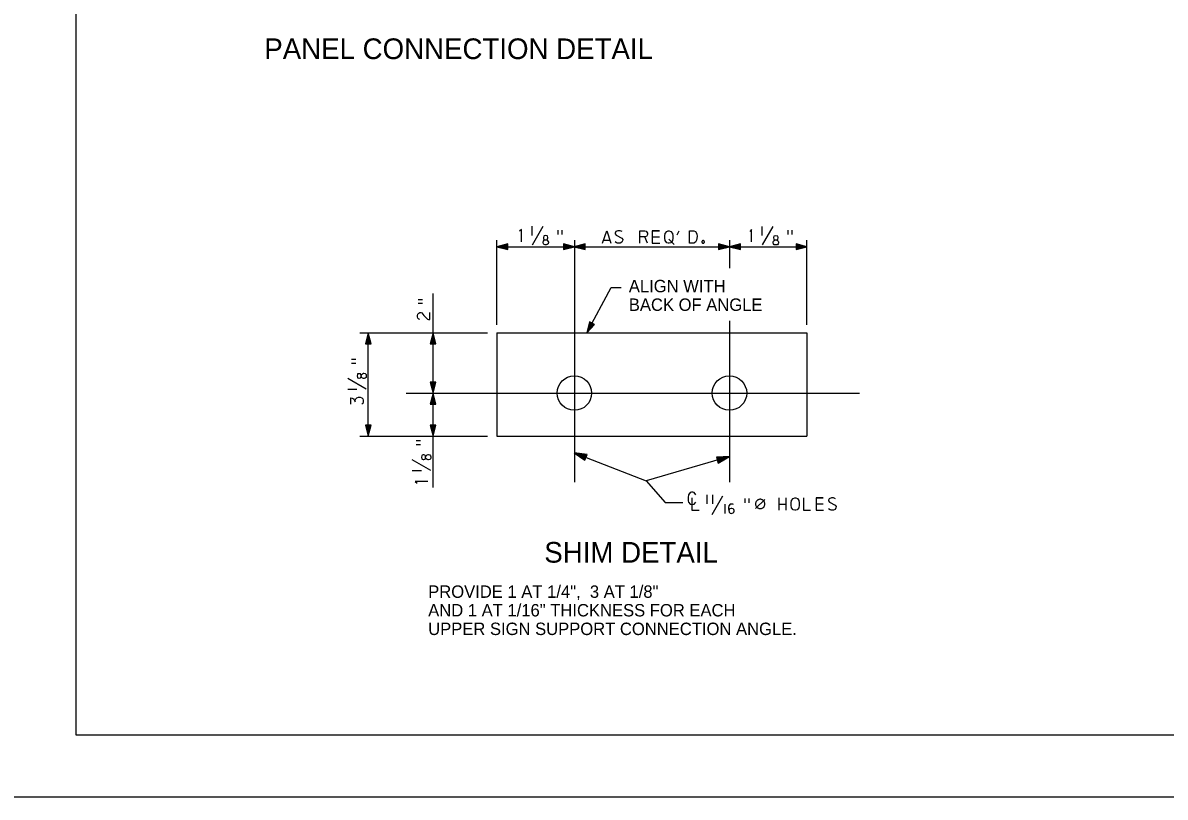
# Model space of a CAD drawing. Extents: x 3831399 to 3833095, y 499014 to 500202.
# Drawn here: x 3832267.3 to 3832543.5, y 499014 to 499201.4 of the extents above; entities that cross this region are included whole.
import ezdxf

# ---------------------------------------------------------------- set-up
doc = ezdxf.new("R2010")
doc.units = 0
for name, color, linetype in [('10', 7, 'Continuous'), ('11', 7, 'Continuous'), ('2', 7, 'Continuous'), ('21', 7, 'Continuous'), ('Default', 7, 'Continuous'), ('PLT-BNDY', 7, 'Continuous')]:
    doc.layers.add(name, color=color, linetype=linetype)

msp = doc.modelspace()

# ---------------------------------------------------------------- linework, layer by layer
at = {"layer": '10'}
for p, q in [((3832390.41, 499149.9), (3832390.41, 499152.15)), ((3832390.53, 499147.63), (3832393.08, 499152.15)), ((3832446.05, 499149.88), (3832446.05, 499152.12)), ((3832446.17, 499147.61), (3832448.72, 499152.12)), ((3832387.89, 499151.39), (3832387.41, 499150.92)), ((3832387.89, 499148.39), (3832387.89, 499151.39)), ((3832396.74, 499150.14), (3832396.74, 499151.2)), ((3832397.69, 499150.14), (3832397.69, 499151.2)), ((3832418.35, 499148.05), (3832417.67, 499149.58)), ((3832419.49, 499151.05), (3832421.21, 499151.05)), ((3832419.49, 499149.56), (3832421.21, 499149.56)), ((3832419.49, 499149.56), (3832421.21, 499149.56)), ((3832425.49, 499150.06), (3832425.96, 499151.05)), ((3832443.52, 499151.36), (3832443.05, 499150.89)), ((3832443.52, 499148.36), (3832443.52, 499151.36)), ((3832452.38, 499150.11), (3832452.38, 499151.17)), ((3832453.33, 499150.11), (3832453.33, 499151.17)), ((3832384.54, 499147.87), (3832381.89, 499147.2)), ((3832381.89, 499147.2), (3832384.54, 499146.54)), ((3832381.9, 499128.27), (3832381.9, 499148.77)), ((3832381.9, 499147.2), (3832400.65, 499147.2)), ((3832384.38, 499147.66), (3832382.54, 499147.2)), ((3832382.54, 499147.2), (3832384.38, 499146.74)), ((3832384.23, 499147.46), (3832383.19, 499147.2)), ((3832383.19, 499147.2), (3832384.23, 499146.94)), ((3832384.16, 499147.29), (3832383.83, 499147.2)), ((3832383.83, 499147.2), (3832384.15, 499147.12)), ((3832384.23, 499146.94), (3832384.23, 499147.46)), ((3832384.38, 499146.74), (3832384.38, 499147.66)), ((3832384.54, 499146.54), (3832384.54, 499147.87)), ((3832400.65, 499147.2), (3832398, 499147.86)), ((3832398, 499147.86), (3832398, 499146.54)), ((3832398, 499146.54), (3832400.65, 499147.2)), ((3832400, 499147.2), (3832398.16, 499147.66)), ((3832398.16, 499147.66), (3832398.16, 499146.74)), ((3832398.16, 499146.74), (3832400, 499147.2)), ((3832399.36, 499147.2), (3832398.32, 499147.46)), ((3832398.32, 499147.46), (3832398.32, 499146.94)), ((3832398.32, 499146.94), (3832399.36, 499147.2)), ((3832398.38, 499147.12), (3832398.71, 499147.2)), ((3832398.71, 499147.2), (3832398.4, 499147.28)), ((3832403.29, 499147.87), (3832400.64, 499147.2)), ((3832400.64, 499147.2), (3832403.29, 499146.54)), ((3832400.65, 499147.2), (3832438.14, 499147.2)), ((3832403.13, 499147.66), (3832401.29, 499147.2)), ((3832401.29, 499147.2), (3832403.13, 499146.74)), ((3832402.97, 499147.46), (3832401.94, 499147.2)), ((3832401.94, 499147.2), (3832402.97, 499146.94)), ((3832402.91, 499147.29), (3832402.58, 499147.2)), ((3832402.58, 499147.2), (3832402.9, 499147.12)), ((3832402.97, 499146.94), (3832402.97, 499147.46)), ((3832403.13, 499146.74), (3832403.13, 499147.66)), ((3832403.29, 499146.54), (3832403.29, 499147.87)), ((3832407.72, 499148.76), (3832409.21, 499148.76)), ((3832424.8, 499147.74), (3832423.48, 499148.99)), ((3832438.15, 499147.2), (3832435.5, 499147.86)), ((3832435.5, 499147.86), (3832435.5, 499146.54)), ((3832435.5, 499146.54), (3832438.15, 499147.2)), ((3832437.5, 499147.2), (3832435.66, 499147.66)), ((3832435.66, 499147.66), (3832435.66, 499146.74)), ((3832435.66, 499146.74), (3832437.5, 499147.2)), ((3832436.85, 499147.2), (3832435.82, 499147.46)), ((3832435.82, 499147.46), (3832435.82, 499146.94)), ((3832435.82, 499146.94), (3832436.85, 499147.2)), ((3832435.88, 499147.12), (3832436.21, 499147.2)), ((3832436.21, 499147.2), (3832435.89, 499147.28)), ((3832440.79, 499147.87), (3832438.14, 499147.2)), ((3832438.14, 499147.2), (3832456.89, 499147.2)), ((3832438.14, 499147.2), (3832440.79, 499146.54)), ((3832440.63, 499147.66), (3832438.79, 499147.2)), ((3832438.79, 499147.2), (3832440.63, 499146.74)), ((3832440.47, 499147.46), (3832439.43, 499147.2)), ((3832439.43, 499147.2), (3832440.47, 499146.94)), ((3832440.41, 499147.29), (3832440.08, 499147.2)), ((3832440.08, 499147.2), (3832440.39, 499147.12)), ((3832440.47, 499146.94), (3832440.47, 499147.46)), ((3832440.63, 499146.74), (3832440.63, 499147.66)), ((3832440.79, 499146.54), (3832440.79, 499147.87)), ((3832456.9, 499147.2), (3832454.25, 499147.86)), ((3832454.25, 499147.86), (3832454.25, 499146.54)), ((3832454.25, 499146.54), (3832456.9, 499147.2)), ((3832456.25, 499147.2), (3832454.41, 499147.66)), ((3832454.41, 499147.66), (3832454.41, 499146.74)), ((3832454.41, 499146.74), (3832456.25, 499147.2)), ((3832455.6, 499147.2), (3832454.57, 499147.46)), ((3832454.57, 499147.46), (3832454.57, 499146.94)), ((3832454.57, 499146.94), (3832455.6, 499147.2)), ((3832454.63, 499147.12), (3832454.96, 499147.2)), ((3832454.96, 499147.2), (3832454.64, 499147.28)), ((3832456.89, 499128.27), (3832456.89, 499148.77)), ((3832366.47, 499126.36), (3832366.47, 499135.86)), ((3832403.67, 499126.36), (3832409.53, 499137.36)), ((3832409.53, 499137.36), (3832411.96, 499137.36)), ((3832363.93, 499134.37), (3832362.87, 499134.37)), ((3832363.93, 499133.42), (3832362.87, 499133.42)), ((3832404.33, 499129), (3832403.67, 499126.36)), ((3832403.67, 499126.36), (3832405.49, 499128.38)), ((3832404.43, 499128.77), (3832403.97, 499126.93)), ((3832403.97, 499126.93), (3832405.24, 499128.33)), ((3832404.53, 499128.53), (3832404.27, 499127.5)), ((3832404.27, 499127.5), (3832404.99, 499128.29)), ((3832405.49, 499128.38), (3832404.33, 499129)), ((3832405.24, 499128.33), (3832404.43, 499128.77)), ((3832404.99, 499128.29), (3832404.53, 499128.53)), ((3832404.66, 499128.4), (3832404.58, 499128.07)), ((3832404.58, 499128.07), (3832404.8, 499128.31)), ((3832348.8, 499126.36), (3832379.65, 499126.36)), ((3832350.82, 499126.36), (3832350.16, 499123.71)), ((3832350.82, 499125.71), (3832350.36, 499123.87)), ((3832350.82, 499125.07), (3832350.56, 499124.03)), ((3832350.82, 499124.42), (3832350.74, 499124.11)), ((3832350.82, 499101.36), (3832350.82, 499126.36)), ((3832351.48, 499123.71), (3832350.82, 499126.36)), ((3832351.28, 499123.87), (3832350.82, 499125.71)), ((3832351.08, 499124.03), (3832350.82, 499125.07)), ((3832350.9, 499124.09), (3832350.82, 499124.42)), ((3832366.47, 499126.36), (3832365.81, 499123.71)), ((3832366.47, 499125.71), (3832366.01, 499123.87)), ((3832366.47, 499125.07), (3832366.21, 499124.03)), ((3832366.47, 499124.42), (3832366.39, 499124.11)), ((3832366.47, 499111.77), (3832366.47, 499126.36)), ((3832367.13, 499123.71), (3832366.47, 499126.36)), ((3832366.93, 499123.87), (3832366.47, 499125.71)), ((3832366.73, 499124.03), (3832366.47, 499125.07)), ((3832366.55, 499124.09), (3832366.47, 499124.42)), ((3832350.16, 499123.71), (3832351.48, 499123.71)), ((3832350.36, 499123.87), (3832351.28, 499123.87)), ((3832350.56, 499124.03), (3832351.08, 499124.03)), ((3832365.81, 499123.71), (3832367.13, 499123.71)), ((3832366.01, 499123.87), (3832366.93, 499123.87)), ((3832366.21, 499124.03), (3832366.73, 499124.03)), ((3832347.83, 499119.91), (3832346.77, 499119.91)), ((3832347.83, 499118.96), (3832346.77, 499118.96)), ((3832350.34, 499112.75), (3832345.83, 499115.3)), ((3832365.8, 499114.42), (3832366.47, 499111.77)), ((3832367.13, 499114.42), (3832365.8, 499114.42)), ((3832366, 499114.26), (3832366.47, 499112.42)), ((3832366.93, 499114.26), (3832366, 499114.26)), ((3832366.21, 499114.1), (3832366.47, 499113.06)), ((3832366.73, 499114.1), (3832366.21, 499114.1)), ((3832366.38, 499114.04), (3832366.47, 499113.71)), ((3832366.47, 499111.77), (3832367.13, 499114.42)), ((3832366.47, 499112.42), (3832366.93, 499114.26)), ((3832366.47, 499113.06), (3832366.73, 499114.1)), ((3832366.47, 499113.71), (3832366.54, 499114.03)), ((3832348.07, 499112.63), (3832345.83, 499112.63)), ((3832366.47, 499111.78), (3832365.81, 499109.13)), ((3832366.47, 499111.13), (3832366.01, 499109.29)), ((3832366.47, 499110.49), (3832366.21, 499109.45)), ((3832367.13, 499109.13), (3832366.47, 499111.78)), ((3832366.47, 499101.36), (3832366.47, 499111.77)), ((3832366.93, 499109.29), (3832366.47, 499111.13)), ((3832366.73, 499109.45), (3832366.47, 499110.49)), ((3832365.81, 499109.13), (3832367.13, 499109.13)), ((3832366.01, 499109.29), (3832366.93, 499109.29)), ((3832366.21, 499109.45), (3832366.73, 499109.45)), ((3832366.47, 499109.84), (3832366.39, 499109.52)), ((3832366.55, 499109.51), (3832366.47, 499109.84)), ((3832350.16, 499104), (3832350.82, 499101.35)), ((3832351.48, 499104), (3832350.16, 499104)), ((3832350.36, 499103.84), (3832350.82, 499102)), ((3832351.28, 499103.84), (3832350.36, 499103.84)), ((3832350.56, 499103.69), (3832350.82, 499102.65)), ((3832351.08, 499103.69), (3832350.56, 499103.69)), ((3832350.73, 499103.62), (3832350.82, 499103.29)), ((3832350.82, 499101.35), (3832351.48, 499104)), ((3832350.82, 499102), (3832351.28, 499103.84)), ((3832350.82, 499102.65), (3832351.08, 499103.69)), ((3832350.82, 499103.29), (3832350.89, 499103.61)), ((3832365.8, 499104), (3832366.47, 499101.35)), ((3832367.13, 499104), (3832365.8, 499104)), ((3832366, 499103.84), (3832366.47, 499102)), ((3832366.93, 499103.84), (3832366, 499103.84)), ((3832366.21, 499103.69), (3832366.47, 499102.65)), ((3832366.73, 499103.69), (3832366.21, 499103.69)), ((3832366.38, 499103.62), (3832366.47, 499103.29)), ((3832366.47, 499101.35), (3832367.13, 499104)), ((3832366.47, 499102), (3832366.93, 499103.84)), ((3832366.47, 499102.65), (3832366.73, 499103.69)), ((3832366.47, 499103.29), (3832366.54, 499103.61)), ((3832348.8, 499101.36), (3832379.65, 499101.36)), ((3832363.43, 499100.23), (3832362.37, 499100.23)), ((3832366.47, 499088.92), (3832366.47, 499101.36)), ((3832363.43, 499099.29), (3832362.37, 499099.29)), ((3832400.64, 499097.3), (3832418, 499090.58)), ((3832400.64, 499097.3), (3832403.17, 499095.52)), ((3832403.71, 499096.92), (3832400.64, 499097.3)), ((3832401.33, 499097.04), (3832403.09, 499095.8)), ((3832403.46, 499096.77), (3832401.33, 499097.04)), ((3832403.22, 499096.63), (3832402.01, 499096.78)), ((3832402.01, 499096.78), (3832403, 499096.07)), ((3832403.09, 499095.8), (3832403.46, 499096.77)), ((3832403.17, 499095.52), (3832403.71, 499096.92)), ((3832365.94, 499093.07), (3832361.42, 499095.63)), ((3832402.69, 499096.51), (3832402.99, 499096.3)), ((3832403.08, 499096.46), (3832402.69, 499096.51)), ((3832403, 499096.07), (3832403.22, 499096.63)), ((3832438.15, 499096.44), (3832418, 499090.58)), ((3832438.15, 499096.44), (3832435.02, 499096.32)), ((3832435.02, 499096.32), (3832435.44, 499094.86)), ((3832437.43, 499096.23), (3832435.25, 499096.15)), ((3832435.25, 499096.15), (3832435.55, 499095.14)), ((3832435.44, 499094.86), (3832438.15, 499096.44)), ((3832436.72, 499096.03), (3832435.49, 499095.98)), ((3832435.49, 499095.98), (3832435.66, 499095.41)), ((3832435.55, 499095.14), (3832437.43, 499096.23)), ((3832436.01, 499095.82), (3832435.64, 499095.81)), ((3832435.66, 499095.41), (3832436.72, 499096.03)), ((3832435.67, 499095.62), (3832436.01, 499095.82)), ((3832363.67, 499092.96), (3832361.42, 499092.96)), ((3832365.18, 499090.43), (3832362.18, 499090.43)), ((3832362.18, 499090.43), (3832362.65, 499089.96)), ((3832418, 499090.58), (3832422.62, 499085.33)), ((3832432.8, 499084.96), (3832432.8, 499087.2)), ((3832434.01, 499082.41), (3832436.56, 499086.92)), ((3832434.1, 499084.96), (3832434.1, 499087.2)), ((3832441.97, 499085.2), (3832441.97, 499086.26)), ((3832442.91, 499085.2), (3832442.91, 499086.26)), ((3832444.47, 499083.83), (3832446.71, 499086.07)), ((3832450.09, 499086.45), (3832450.09, 499083.45)), ((3832451.79, 499086.45), (3832451.79, 499083.45)), ((3832459.09, 499086.45), (3832460.82, 499086.45)), ((3832422.62, 499085.33), (3832426.86, 499085.33)), ((3832437.08, 499082.69), (3832437.08, 499084.94)), ((3832450.09, 499084.94), (3832451.79, 499084.94)), ((3832459.09, 499084.96), (3832460.82, 499084.96)), ((3832459.09, 499084.96), (3832460.82, 499084.96))]:
    msp.add_line(p, q, dxfattribs=at)
for points in [[(3832393.84, 499148.89), (3832394.1, 499148.96), (3832394.19, 499149.07), (3832394.26, 499149.33), (3832394.26, 499149.45), (3832394.19, 499149.74), (3832394.08, 499149.81), (3832393.72, 499149.88), (3832393.34, 499149.81), (3832393.25, 499149.74), (3832393.15, 499149.45), (3832393.15, 499149.33), (3832393.22, 499149.07), (3832393.34, 499148.96), (3832393.6, 499148.89), (3832393.84, 499148.89), (3832394.1, 499148.74), (3832394.26, 499148.53), (3832394.36, 499148.29), (3832394.36, 499148.2), (3832394.29, 499147.89), (3832394.1, 499147.7), (3832393.84, 499147.63), (3832393.6, 499147.63), (3832393.34, 499147.7), (3832393.15, 499147.89), (3832393.08, 499148.18), (3832393.08, 499148.29), (3832393.18, 499148.53), (3832393.34, 499148.74), (3832393.6, 499148.89)], [(3832407.49, 499148.05), (3832408.48, 499151.05), (3832409.45, 499148.05)], [(3832412.21, 499150.84), (3832411.74, 499151.05), (3832411.19, 499151.05), (3832410.7, 499150.84), (3832410.49, 499150.46), (3832410.49, 499150.32), (3832410.72, 499149.96), (3832412.09, 499149.25), (3832412.33, 499148.92), (3832412.31, 499148.64), (3832412.09, 499148.26), (3832411.69, 499148.05), (3832411.12, 499148.05), (3832410.86, 499148.14), (3832410.49, 499148.4)], [(3832416.49, 499148.05), (3832416.49, 499151.05), (3832417.69, 499151.05), (3832418.05, 499150.93), (3832418.35, 499150.46), (3832418.35, 499150.17), (3832418.07, 499149.7), (3832417.69, 499149.58), (3832416.49, 499149.58)], [(3832421.21, 499151.05), (3832419.49, 499151.05), (3832419.49, 499148.05), (3832421.33, 499148.05)], [(3832423.34, 499151.05), (3832423.57, 499151.05), (3832423.97, 499150.88), (3832424.35, 499150.39), (3832424.45, 499149.8), (3832424.45, 499149.25), (3832424.35, 499148.66), (3832423.95, 499148.17), (3832423.57, 499148.05), (3832423.34, 499148.05), (3832422.98, 499148.17), (3832422.58, 499148.66), (3832422.49, 499149.25), (3832422.49, 499149.8), (3832422.58, 499150.41), (3832422.98, 499150.91), (3832423.34, 499151.05)], [(3832428.49, 499151.05), (3832429.57, 499151.05), (3832429.97, 499150.84), (3832430.23, 499150.32), (3832430.35, 499149.63), (3832430.21, 499148.78), (3832429.95, 499148.26), (3832429.57, 499148.05), (3832428.49, 499148.05), (3832428.49, 499151.05)], [(3832449.48, 499148.86), (3832449.74, 499148.93), (3832449.83, 499149.05), (3832449.9, 499149.31), (3832449.9, 499149.43), (3832449.83, 499149.71), (3832449.71, 499149.78), (3832449.36, 499149.85), (3832448.98, 499149.78), (3832448.89, 499149.71), (3832448.79, 499149.43), (3832448.79, 499149.31), (3832448.86, 499149.05), (3832448.98, 499148.93), (3832449.24, 499148.86), (3832449.48, 499148.86), (3832449.74, 499148.72), (3832449.9, 499148.51), (3832450, 499148.27), (3832450, 499148.17), (3832449.92, 499147.87), (3832449.74, 499147.68), (3832449.48, 499147.61), (3832449.24, 499147.61), (3832448.98, 499147.68), (3832448.79, 499147.87), (3832448.72, 499148.15), (3832448.72, 499148.27), (3832448.81, 499148.51), (3832448.98, 499148.72), (3832449.24, 499148.86)], [(3832432.1, 499148.36), (3832432.1, 499148.39), (3832432.09, 499148.42), (3832432.08, 499148.45), (3832432.07, 499148.48), (3832432.06, 499148.51), (3832432.04, 499148.54), (3832432.02, 499148.56), (3832432, 499148.58), (3832431.97, 499148.6), (3832431.95, 499148.62), (3832431.92, 499148.64), (3832431.89, 499148.65), (3832431.86, 499148.66), (3832431.82, 499148.66), (3832431.79, 499148.66), (3832431.76, 499148.66), (3832431.73, 499148.66), (3832431.7, 499148.65), (3832431.67, 499148.64), (3832431.64, 499148.62), (3832431.61, 499148.6), (3832431.59, 499148.58), (3832431.56, 499148.56), (3832431.54, 499148.54), (3832431.53, 499148.51), (3832431.51, 499148.48), (3832431.5, 499148.45), (3832431.49, 499148.42), (3832431.49, 499148.39), (3832431.49, 499148.36), (3832431.49, 499148.32), (3832431.49, 499148.29), (3832431.5, 499148.26), (3832431.51, 499148.23), (3832431.53, 499148.2), (3832431.54, 499148.17), (3832431.56, 499148.15), (3832431.59, 499148.13), (3832431.61, 499148.11), (3832431.64, 499148.09), (3832431.67, 499148.07), (3832431.7, 499148.06), (3832431.73, 499148.05), (3832431.76, 499148.05), (3832431.79, 499148.05), (3832431.82, 499148.05), (3832431.86, 499148.05), (3832431.89, 499148.06), (3832431.92, 499148.07), (3832431.95, 499148.09), (3832431.97, 499148.11), (3832432, 499148.13), (3832432.02, 499148.15), (3832432.04, 499148.17), (3832432.06, 499148.2), (3832432.07, 499148.23), (3832432.08, 499148.26), (3832432.09, 499148.29), (3832432.1, 499148.32), (3832432.1, 499148.36)], [(3832363.29, 499129.55), (3832363.01, 499129.65), (3832362.77, 499129.91), (3832362.68, 499130.26), (3832362.68, 499130.52), (3832362.77, 499130.87), (3832363.03, 499131.13), (3832363.29, 499131.25), (3832363.55, 499131.25), (3832363.77, 499131.16), (3832364.21, 499130.57), (3832365.16, 499129.65), (3832365.4, 499129.55), (3832365.68, 499129.55), (3832365.68, 499131.25)], [(3832349.09, 499116.06), (3832349.02, 499116.31), (3832348.9, 499116.41), (3832348.64, 499116.48), (3832348.52, 499116.48), (3832348.24, 499116.41), (3832348.17, 499116.29), (3832348.09, 499115.94), (3832348.17, 499115.56), (3832348.24, 499115.46), (3832348.52, 499115.37), (3832348.64, 499115.37), (3832348.9, 499115.44), (3832349.02, 499115.56), (3832349.09, 499115.82), (3832349.09, 499116.06), (3832349.23, 499116.31), (3832349.44, 499116.48), (3832349.68, 499116.57), (3832349.77, 499116.57), (3832350.08, 499116.5), (3832350.27, 499116.31), (3832350.34, 499116.06), (3832350.34, 499115.82), (3832350.27, 499115.56), (3832350.08, 499115.37), (3832349.8, 499115.3), (3832349.68, 499115.3), (3832349.44, 499115.39), (3832349.23, 499115.56), (3832349.09, 499115.82)], [(3832346.58, 499109.09), (3832346.58, 499110.67), (3832346.94, 499110.57), (3832347.2, 499110.41), (3832347.43, 499110.17), (3832347.67, 499109.7), (3832347.67, 499110.06), (3832347.83, 499110.43), (3832348.07, 499110.67), (3832348.45, 499110.79), (3832348.85, 499110.79), (3832349.25, 499110.67), (3832349.49, 499110.41), (3832349.58, 499110.06), (3832349.58, 499109.65), (3832349.49, 499109.3), (3832349.23, 499109.09)], [(3832364.68, 499096.38), (3832364.61, 499096.64), (3832364.49, 499096.74), (3832364.23, 499096.81), (3832364.12, 499096.81), (3832363.83, 499096.74), (3832363.76, 499096.62), (3832363.69, 499096.26), (3832363.76, 499095.89), (3832363.83, 499095.79), (3832364.12, 499095.7), (3832364.23, 499095.7), (3832364.49, 499095.77), (3832364.61, 499095.89), (3832364.68, 499096.15), (3832364.68, 499096.38), (3832364.82, 499096.64), (3832365.04, 499096.81), (3832365.27, 499096.9), (3832365.37, 499096.9), (3832365.68, 499096.83), (3832365.86, 499096.64), (3832365.94, 499096.38), (3832365.94, 499096.15), (3832365.86, 499095.89), (3832365.68, 499095.7), (3832365.39, 499095.63), (3832365.27, 499095.63), (3832365.04, 499095.72), (3832364.82, 499095.89), (3832364.68, 499096.15)], [(3832430.02, 499087.2), (3832429.65, 499087.7), (3832429.27, 499087.79), (3832429.01, 499087.79), (3832428.65, 499087.7), (3832428.25, 499087.2), (3832428.16, 499086.54), (3832428.16, 499086.19), (3832428.16, 499085.95), (3832428.18, 499085.74), (3832428.25, 499085.36), (3832428.65, 499084.89), (3832429.01, 499084.79), (3832429.22, 499084.79), (3832429.62, 499084.89), (3832430.02, 499085.36)], [(3832429.09, 499086.45), (3832429.09, 499083.45), (3832430.79, 499083.45)], [(3832446.72, 499084.96), (3832446.71, 499085.08), (3832446.7, 499085.19), (3832446.66, 499085.31), (3832446.62, 499085.42), (3832446.57, 499085.52), (3832446.51, 499085.62), (3832446.43, 499085.71), (3832446.35, 499085.8), (3832446.26, 499085.87), (3832446.16, 499085.93), (3832446.05, 499085.99), (3832445.94, 499086.03), (3832445.83, 499086.06), (3832445.71, 499086.08), (3832445.6, 499086.09), (3832445.48, 499086.08), (3832445.36, 499086.06), (3832445.25, 499086.03), (3832445.14, 499085.99), (3832445.03, 499085.93), (3832444.93, 499085.87), (3832444.84, 499085.8), (3832444.76, 499085.71), (3832444.68, 499085.62), (3832444.62, 499085.52), (3832444.57, 499085.42), (3832444.52, 499085.31), (3832444.49, 499085.19), (3832444.48, 499085.08), (3832444.47, 499084.96), (3832444.48, 499084.84), (3832444.49, 499084.73), (3832444.52, 499084.61), (3832444.57, 499084.5), (3832444.62, 499084.4), (3832444.68, 499084.3), (3832444.76, 499084.21), (3832444.84, 499084.12), (3832444.93, 499084.05), (3832445.03, 499083.99), (3832445.14, 499083.93), (3832445.25, 499083.89), (3832445.36, 499083.86), (3832445.48, 499083.84), (3832445.6, 499083.84), (3832445.71, 499083.84), (3832445.83, 499083.86), (3832445.94, 499083.89), (3832446.05, 499083.93), (3832446.16, 499083.99), (3832446.26, 499084.05), (3832446.35, 499084.12), (3832446.43, 499084.21), (3832446.51, 499084.3), (3832446.57, 499084.4), (3832446.62, 499084.5), (3832446.66, 499084.61), (3832446.7, 499084.73), (3832446.71, 499084.84), (3832446.72, 499084.96)], [(3832453.94, 499086.45), (3832454.18, 499086.45), (3832454.58, 499086.28), (3832454.96, 499085.79), (3832455.05, 499085.2), (3832455.05, 499084.65), (3832454.96, 499084.06), (3832454.56, 499083.57), (3832454.18, 499083.45), (3832453.94, 499083.45), (3832453.59, 499083.57), (3832453.19, 499084.06), (3832453.09, 499084.65), (3832453.09, 499085.2), (3832453.19, 499085.81), (3832453.59, 499086.31), (3832453.94, 499086.45)], [(3832456.09, 499086.45), (3832456.09, 499083.45), (3832457.79, 499083.45)], [(3832460.82, 499086.45), (3832459.09, 499086.45), (3832459.09, 499083.45), (3832460.93, 499083.45)], [(3832463.82, 499086.24), (3832463.34, 499086.45), (3832462.8, 499086.45), (3832462.3, 499086.24), (3832462.09, 499085.86), (3832462.09, 499085.72), (3832462.33, 499085.36), (3832463.7, 499084.65), (3832463.93, 499084.32), (3832463.91, 499084.04), (3832463.7, 499083.66), (3832463.3, 499083.45), (3832462.73, 499083.45), (3832462.47, 499083.54), (3832462.09, 499083.8)], [(3832439.13, 499084.8), (3832439.01, 499084.87), (3832438.8, 499084.94), (3832438.59, 499084.94), (3832438.31, 499084.87), (3832438, 499084.49), (3832437.93, 499084.13), (3832437.93, 499083.73), (3832437.97, 499083.4), (3832438.12, 499082.95), (3832438.31, 499082.76), (3832438.59, 499082.69), (3832439.04, 499082.79), (3832439.23, 499082.95), (3832439.32, 499083.24), (3832439.32, 499083.38), (3832439.23, 499083.59), (3832439.04, 499083.8), (3832438.75, 499083.87), (3832438.56, 499083.9), (3832438.28, 499083.8), (3832438.12, 499083.59), (3832438.02, 499083.24)]]:
    msp.add_lwpolyline(points, dxfattribs=at)
at = {"layer": '11'}
for p, q in [((3832400.65, 499148.77), (3832400.65, 499090.27)), ((3832438.15, 499148.78), (3832438.15, 499142.02)), ((3832438.15, 499129.27), (3832438.15, 499090.27)), ((3832359.96, 499111.77), (3832469.57, 499111.77))]:
    msp.add_line(p, q, dxfattribs=at)
at = {"layer": '2'}
for p, q in [((3832280.16, 499029.03), (3832280.16, 499593.03)), ((3833066.16, 499029.03), (3832280.16, 499029.03))]:
    msp.add_line(p, q, dxfattribs=at)
at = {"layer": '21'}
for p, q in [((3832381.9, 499126.36), (3832456.89, 499126.36)), ((3832381.9, 499126.36), (3832381.9, 499101.36)), ((3832456.89, 499126.36), (3832456.89, 499101.36)), ((3832381.9, 499101.36), (3832456.89, 499101.36))]:
    msp.add_line(p, q, dxfattribs=at)
for centre in [(3832400.65, 499111.78), (3832438.15, 499111.78)]:
    msp.add_circle(centre, 4.17, dxfattribs=at)
at = {"layer": 'PLT-BNDY'}
msp.add_lwpolyline([(3832240.16, 499608.03), (3833081.16, 499608.03), (3833081.16, 499014.03), (3832240.16, 499014.03)], close=True, dxfattribs=at)

# ---------------------------------------------------------------- texts
at = {"layer": '10'}
for s, p in [('ALIGN WITH ', (3832413.82, 499136.17)), ('BACK OF ANGLE', (3832413.82, 499131.67)), ('PROVIDE 1 AT 1/4",  3 AT 1/8"', (3832365.3, 499062.25)), ('AND 1 AT 1/16" THICKNESS FOR EACH', (3832365.3, 499057.75)), ('UPPER SIGN SUPPORT CONNECTION ANGLE.', (3832365.3, 499053.25))]:
    msp.add_text(s, height=2.9999, dxfattribs=at).set_placement(p)
at = {"layer": 'Default'}
for s, p in [('PANEL CONNECTION DETAIL', (3832325.67, 499192.58)), ('SHIM DETAIL', (3832393.38, 499070.76))]:
    msp.add_text(s, height=4.9999, dxfattribs=at).set_placement(p)

doc.saveas('drawing.dxf')
